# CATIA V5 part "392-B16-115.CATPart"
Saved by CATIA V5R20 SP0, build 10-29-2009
Part number: 392-B16-115
Definition: NONE
Nomenclature: 392-B16-115
Source: Unknown
Description: 392-B16-115
Bounding box of the stored display mesh (mm): x 0 to 115, y -7.675 to 7.675, z -7.6 to 7.409
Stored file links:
  C:\Users\Utente\Desktop\IO LAVORO\3D X SITO CF\X SITO\3D files 392B\392-B16-115.CATPart
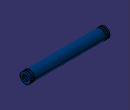
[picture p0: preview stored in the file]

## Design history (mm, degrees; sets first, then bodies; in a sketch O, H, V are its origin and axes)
Body1 "392-B16-115" (main body)
  Solid1: solid without history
